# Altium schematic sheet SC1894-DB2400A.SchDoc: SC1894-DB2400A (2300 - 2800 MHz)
size B; Organization: Maxim Integrated; Address1: 160 Rio Robles; Address2: San Jose, CA. 95134; Address3: U.S.A.; Address4: 408-601-1000; Revision: 2.0; SheetNumber: 1; SheetTotal: 1; PageSetup: Record=PageOptions¦CenterHorizontal=True¦CenterVertical=True¦PrintScale=1.12¦XCorrection=1.00¦YCorrection=1.00¦PrintKind=1¦BorderSize=5000000¦LeftOffset=0¦BottomOffset=0¦Orientation=2¦PaperLength=1000¦PaperWidth=1000¦Scale=100¦PaperSource=15¦PrintQuality=600¦MediaType=1¦DitherType=10¦PaperKind=Tabloid¦PrintScaleMode=1
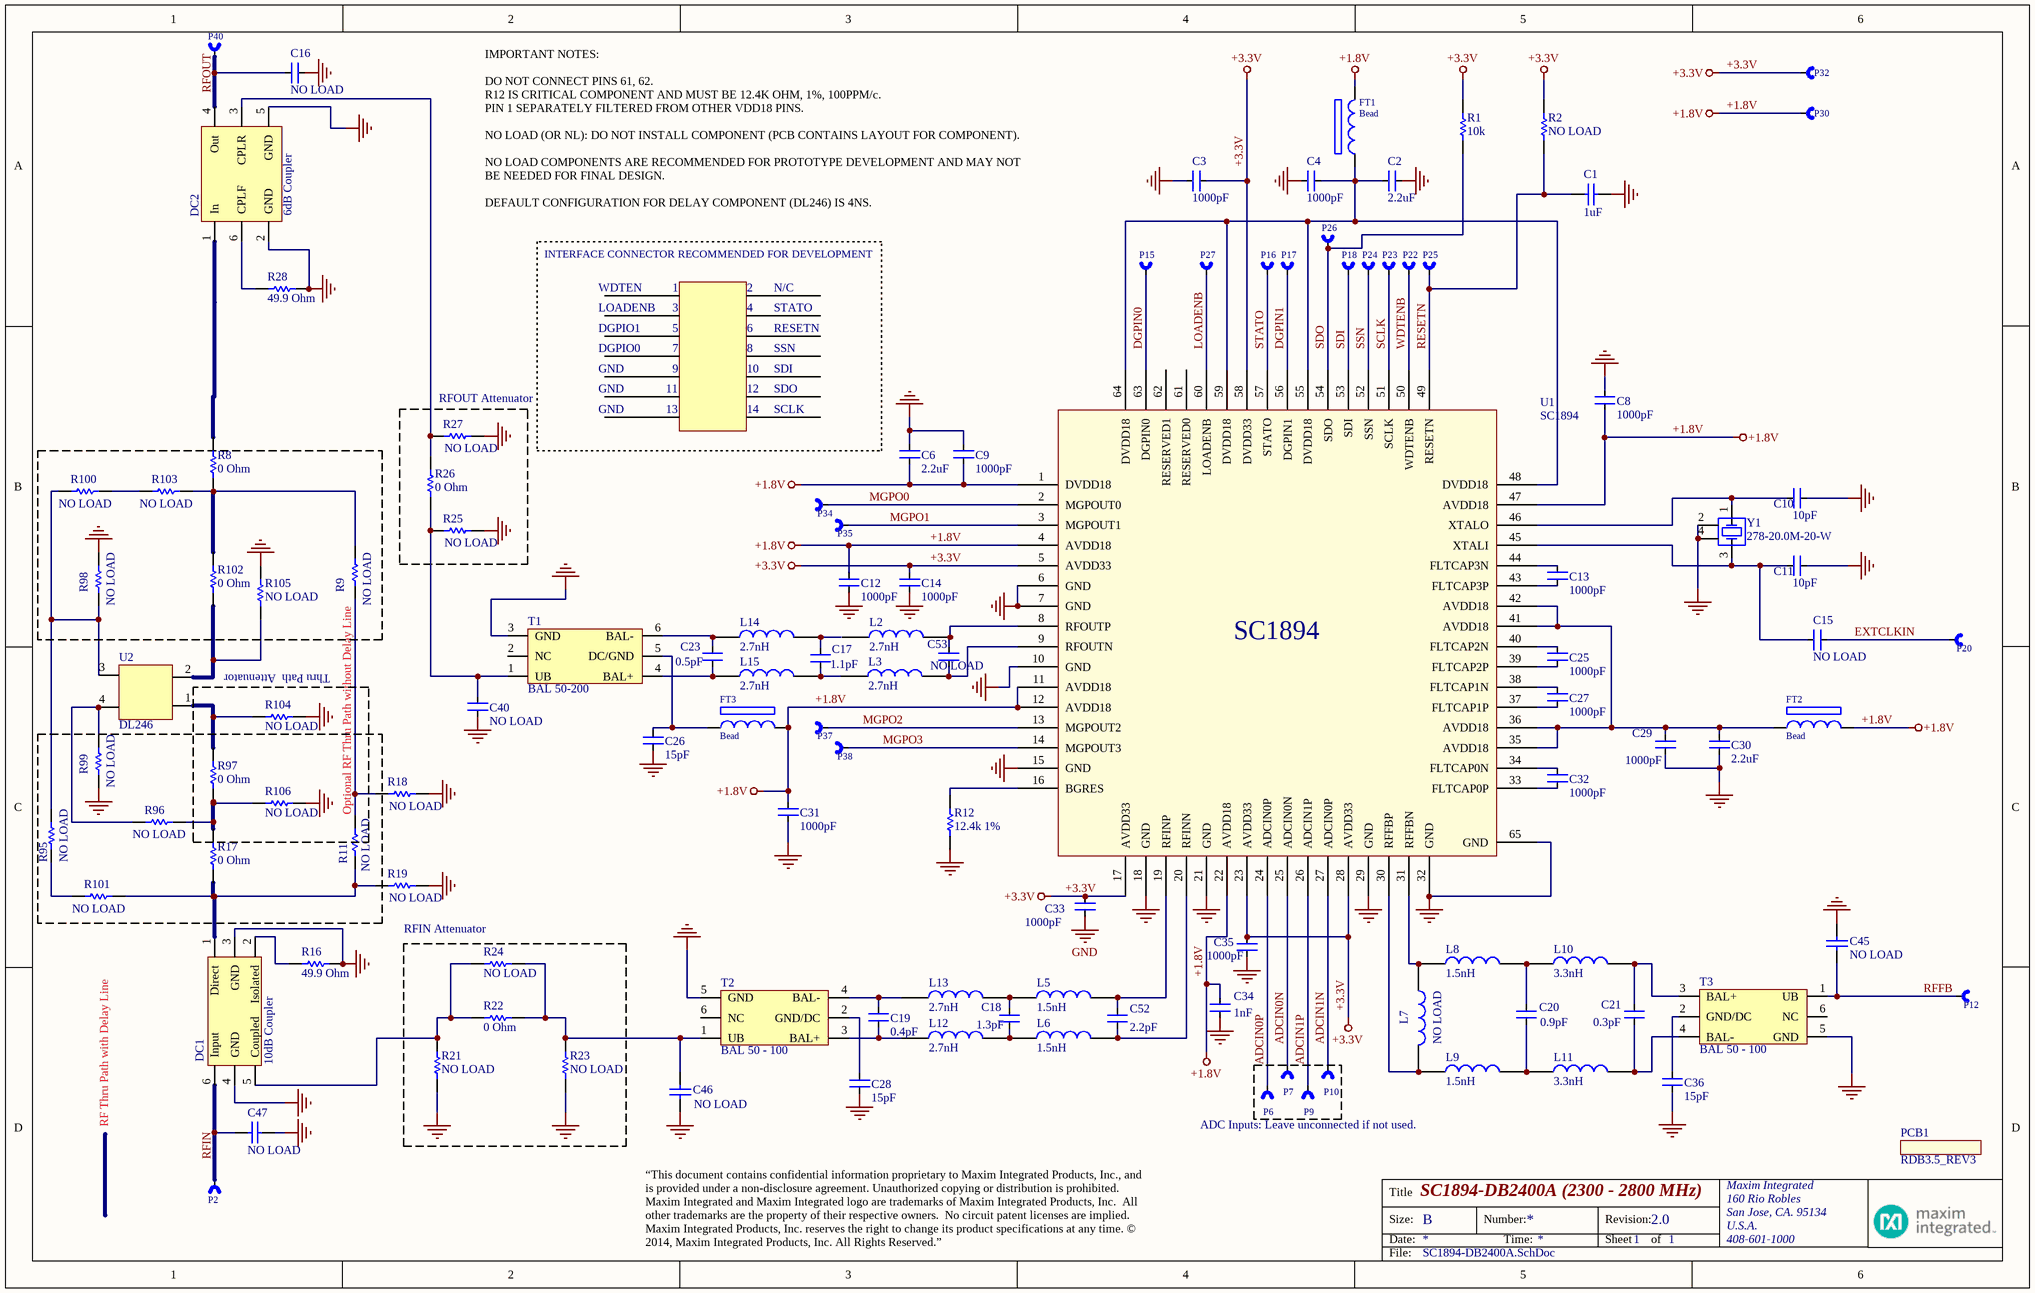
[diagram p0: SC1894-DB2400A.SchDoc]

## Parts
C1  1uF  [1608[0603]]
C2  2.2uF  [0603 SMD]
C3  1000pF  [0402 SMD]
C4  1000pF  [0402 SMD]
C6  2.2uF  [0603 SMD]
C8  1000pF  [0402 SMD]
C9  1000pF  [0402 SMD]
C10  10pF  [0402 SMD]
C11  10pF  [0402 SMD]
C12  1000pF  [0402 SMD]
C13  1000pF  [0402 SMD]
C14  1000pF  [0402 SMD]
C15  NO LOAD  [0402 SMD]
C16  NO LOAD  [0402 SMD]
C17  1.1pF  [0402 SMD]
C18  1.3pF  [0402 SMD]
C19  0.4pF  [0402 SMD]
C20  0.9pF  [0402 SMD]
C21  0.3pF  [0402 SMD]
C23  0.5pF  [0402 SMD]
C25  1000pF  [0402 SMD]
C26  15pF  [0402 SMD]
C27  1000pF  [0402 SMD]
C28  15pF  [0402 SMD]
C29  1000pF  [0402 SMD]
C30  2.2uF  [0603 SMD]
C31  1000pF  [0402 SMD]
C32  1000pF  [0402 SMD]
C33  1000pF  [0402 SMD]
C34  1nF  [0402 SMD]
C35  1000pF  [0402 SMD]
C36  15pF  [0402 SMD]
C40  NO LOAD  [0402 SMD]
C45  NO LOAD  [0402 SMD]
C46  NO LOAD  [0402 SMD]
C47  NO LOAD  [0402 SMD]
C52  2.2pF  [0402 SMD]
C53  NO LOAD  [0402 SMD]
DC1  10dB Coupler  [0805 COUPLER ANAREN]
DC2  6dB Coupler  [BDCN-7-25+]
FT1  Bead  [0603 SMD]
FT2  Bead  [0603 SMD]
FT3  Bead  [0402 SMD]
L2  2.7nH  [0402 SMD]
L3  2.7nH  [0402 SMD]
L5  1.5nH  [0402 SMD]
L6  1.5nH  [0402 SMD]
L7  NO LOAD  [0402 SMD]
L8  1.5nH  [0402 SMD]
L9  1.5nH  [0402 SMD]
L10  3.3nH  [0402 SMD]
L11  3.3nH  [0402 SMD]
L12  2.7nH  [0402 SMD]
L13  2.7nH  [0402 SMD]
L14  2.7nH  [0402 SMD]
L15  2.7nH  [0402 SMD]
P2  PORT 1-M  [PORT-1_M-PAD]  (value not drawn)
P6  PORT 1-M  [PORT-1_M-PAD]  (value not drawn)
P7  PORT 1-M  [PORT-1_M-PAD]  (value not drawn)
P9  PORT 1-M  [PORT-1_M-PAD]  (value not drawn)
P10  PORT 1-M  [PORT-1_M-PAD]  (value not drawn)
P12  PORT 1-M  [PORT-1_M-PAD]  (value not drawn)
P15  PORT 1-M  [PORT-1_M-PAD]  (value not drawn)
P16  PORT 1-M  [PORT-1_M-PAD]  (value not drawn)
P17  PORT 1-M  [PORT-1_M-PAD]  (value not drawn)
P18  PORT 1-M  [PORT-1_M-PAD]  (value not drawn)
P20  PORT 1-M  [PORT-1_M-PAD]  (value not drawn)
P22  PORT 1-M  [PORT-1_M-PAD]  (value not drawn)
P23  PORT 1-M  [PORT-1_M-PAD]  (value not drawn)
P24  PORT 1-M  [PORT-1_M-PAD]  (value not drawn)
P25  PORT 1-M  [PORT-1_M-PAD]  (value not drawn)
P26  PORT 1-M  [PORT-1_M-PAD]  (value not drawn)
P27  PORT 1-M  [PORT-1_M-PAD]  (value not drawn)
P30  PORT 1-M  [PORT-1_M-PAD]  (value not drawn)
P32  PORT 1-M  [PORT-1_M-PAD]  (value not drawn)
P34  PORT 1-M  [PORT-1_M-PAD]  (value not drawn)
P35  PORT 1-M  [PORT-1_M-PAD]  (value not drawn)
P37  PORT 1-M  [PORT-1_M-PAD]  (value not drawn)
P38  PORT 1-M  [PORT-1_M-PAD]  (value not drawn)
P40  PORT 1-M  [PORT-1_M-PAD]  (value not drawn)
PCB1  RDB3.5_REV3
R1  10k  [0402 SMD]
R2  NO LOAD  [0402 SMD]
R8  0 Ohm  [0402 SMD]
R9  NO LOAD  [0402 SMD]
R11  NO LOAD  [0402 SMD]
R12  12.4k 1%  [0402 SMD]
R16  49.9 Ohm  [0402 SMD]
R17  0 Ohm  [0402 SMD]
R18  NO LOAD  [0402 SMD]
R19  NO LOAD  [0402 SMD]
R21  NO LOAD  [0402 SMD]
R22  0 Ohm  [0201_SMT]
R23  NO LOAD  [0402 SMD]
R24  NO LOAD  [0201_SMT]
R25  NO LOAD  [0402 SMD]
R26  0 Ohm  [0402 SMD]
R27  NO LOAD  [0402 SMD]
R28  49.9 Ohm  [0402 SMD]
R95  NO LOAD  [0402 SMD]
R96  NO LOAD  [0402 SMD]
R97  0 Ohm  [0402 SMD]
R98  NO LOAD  [0402 SMD]
R99  NO LOAD  [0402 SMD]
R100  NO LOAD  [0402 SMD]
R101  NO LOAD  [0402 SMD]
R102  0 Ohm  [0402 SMD]
R103  NO LOAD  [0402 SMD]
R104  NO LOAD  [0402 SMD]
R105  NO LOAD  [0402 SMD]
R106  NO LOAD  [0402 SMD]
T1  BAL 50-200
T2  BAL 50 - 100  [0805 BALUN Anaren]
T3  BAL 50 - 100  [0805 BALUN Anaren]
U1  SC1894  [SC1894]
U2  DL246  [DL246-A]
Y1  278-20.0M-20-W  [278-20.0M]

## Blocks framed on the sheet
RFOUT Attenuator: R25-R27
Optional RF Thru Path without Delay Line: R11 R17 R95-R97 R99 R101 R106
RFIN Attenuator: R21-R24

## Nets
+1.8V: C6.2 C8.2 C9.2 C12.1 C31.2 C34.2 FT1.2 FT2.2 FT3.2 P30.1(P*) U1.1(DVDD18) U1.4(AVDD18) U1.11(AVDD18) U1.12(AVDD18) U1.22(AVDD18) U1.47(AVDD18)
+3.3V: C3.2 C14.1 C33.1 C35.2 P32.1(P*) R1.2 R2.2 U1.5(AVDD33) U1.17(AVDD33) U1.23(AVDD33) U1.28(AVDD33) U1.58(DVDD33)
GND: C1.1 C2.2 C3.1 C4.1 C6.1 C8.1 C9.1 C10.2 C11.2 C12.2 C14.2 C16.2 C26.2 C28.2 C29.2 C30.2 C31.1 C33.2 C34.1 C35.1 C36.2 C40.2 C45.1 C46.1 C47.1 DC1.3(GND) DC1.4(GND) DC2.2(GND) DC2.5(GND) R12.1 R16.2 R18.2 R19.2 R21.1 R23.1 R25.2 R27.2 R28.2 R98.1 R99.2 R104.2 R105.1 R106.2 T1.3(GND) T2.5(GND) T3.5(GND) U1.6(GND) U1.7(GND) U1.10(GND) U1.15(GND) U1.18(GND) U1.21(GND) U1.29(GND) U1.32(GND) U1.65(GND) Y1.2(SHIELD1) Y1.4(SHIELD2)
ADCIN0N: P7.1(P*) U1.25(ADCIN0N)
ADCIN0P: P6.1(P*) U1.24(ADCIN0P)
ADCIN1N: P10.1(P*) U1.27(ADCIN0P)
ADCIN1P: P9.1(P*) U1.26(ADCIN1P)
DGPIN0: P15.1(P*) U1.63(DGPIN0)
DGPIN1: P17.1(P*) U1.56(DGPIN1)
EXTCLKIN: C15.2 P20.1(P*)
LOADENB: P27.1(P*) U1.60(LOADENB)
MGPO0: P34.1(P*) U1.2(MGPOUT0)
MGPO1: P35.1(P*) U1.3(MGPOUT1)
MGPO2: P37.1(P*) U1.13(MGPOUT2)
MGPO3: P38.1(P*) U1.14(MGPOUT3)
RESETN: C1.2 P25.1(P*) R2.1 U1.49(RESETN)
RFFB: C45.2 P12.1(P*) T3.1(UB)
RFIN: C47.2 DC1.6(Input) P2.1(P*)
RFOUT: C16.1 DC2.4(Out) P40.1(P*)
SCLK: P23.1(P*) U1.51(SCLK)
SDI: P18.1(P*) U1.53(SDI)
SDO: P26.1(P*) R1.1 U1.54(SDO)
SSN: P24.1(P*) U1.52(SSN)
STATO: P16.1(P*) U1.57(STATO)
WDTENB: P22.1(P*) U1.50(WDTENB)
NetC2_1: C2.1 C4.2 FT1.1 U1.48(DVDD18) U1.55(DVDD18) U1.59(DVDD18) U1.64(DVDD18)
NetC10_1: C10.1 U1.46(XTALO) Y1.1(OSC1)
NetC11_1: C11.1 C15.1 U1.45(XTALI) Y1.3(OSC2)
NetC13_1: C13.1 U1.44(FLTCAP3N)
NetC13_2: C13.2 U1.43(FLTCAP3P)
NetC17_1: C17.1 L14.2
NetC17_2: C17.2 L3.1 L15.2
NetC18_1: C18.1 L5.1 L13.2
NetC18_2: C18.2 L6.1 L12.2
NetC19_1: C19.1 L13.1 T2.4(BAL-)
NetC19_2: C19.2 L12.1 T2.3(BAL+)
NetC20_1: C20.1 L8.2 L10.1
NetC20_2: C20.2 L9.2 L11.1
NetC21_1: C21.1 L10.2 T3.3(BAL+)
NetC21_2: C21.2 L11.2 T3.4(BAL-)
NetC23_1: C23.1 L14.1 T1.6(BAL-)
NetC23_2: C23.2 L15.1 T1.4(BAL+)
NetC25_1: C25.1 U1.40(FLTCAP2N)
NetC25_2: C25.2 U1.39(FLTCAP2P)
NetC26_1: C26.1 FT3.1 T1.5(DC/GND)
NetC27_1: C27.1 U1.38(FLTCAP1N)
NetC27_2: C27.2 U1.37(FLTCAP1P)
NetC28_1: C28.1 T2.2(GND/DC)
NetC29_1: C29.1 C30.1 FT2.1 U1.35(AVDD18) U1.36(AVDD18) U1.41(AVDD18) U1.42(AVDD18)
NetC32_1: C32.1 U1.34(FLTCAP0N)
NetC32_2: C32.2 U1.33(FLTCAP0P)
NetC36_1: C36.1 T3.2(GND/DC)
NetC40_1: C40.1 R25.1 R26.1 T1.1(UB)
NetC46_2: C46.2 R22.2 R23.2 R24.2 T2.1(UB)
NetC52_1: C52.1 L5.2 U1.19(RFINP)
NetC52_2: C52.2 L6.2 U1.20(RFINN)
NetC53_1: C53.1 L2.2 U1.8(RFOUTP)
NetC53_2: C53.2 L3.2 U1.9(RFOUTN)
NetDC1_1: DC1.1(Direct) R11.1 R17.1 R19.1 R101.1
NetDC1_2: DC1.2(Isolated) R16.1
NetDC1_5: DC1.5(Coupled) R21.2 R22.1 R24.1
NetDC2_1: DC2.1(In) R8.2
NetDC2_3: DC2.3(CPLR) R26.2 R27.1
NetDC2_6: DC2.6(CPLF) R28.1
NetL7_1: L7.1 L8.1 U1.31(RFFBN)
NetL7_2: L7.2 L9.1 U1.30(RFFBP)
NetR8_1: R8.1 R9.2 R102.2 R103.2
NetR9_1: R9.1 R11.2 R18.1
NetR12_2: R12.2 U1.16(BGRES)
NetR17_2: R17.2 R96.1 R97.1 R106.1
NetR95_1: R95.1 R98.2 R100.1 U2.3(2ns_B)
NetR95_2: R95.2 R101.2
NetR96_2: R96.2 R99.1 U2.4(2ns_A)
NetR97_2: R97.2 R104.1 U2.1(4ns_A)
NetR100_2: R100.2 R103.1
NetR102_1: R102.1 R105.2 U2.2(4ns_B)

Not connected (* = marked no-connect by the designer): L2 1; T1 2(NC); T2 6(NC); T3 6(NC); U1 61(RESERVED0) 62(RESERVED1)

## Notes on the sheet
- IMPORTANT NOTES:
  DO NOT CONNECT PINS 61, 62.
  R12 IS CRITICAL COMPONENT AND MUST BE 12.4K OHM, 1%, 100PPM/c.
  PIN 1 SEPARATELY FILTERED FROM OTHER VDD18 PINS.
  NO LOAD (OR NL): DO NOT INSTALL COMPONENT (PCB CONTAINS LAYOUT FOR COMPONENT).
  NO LOAD COMPONENTS ARE RECOMMENDED FOR PROTOTYPE DEVELOPMENT AND MAY NOT BE NEEDED FOR FINAL DESIGN.
  DEFAULT CONFIGURATION FOR DELAY COMPONENT (DL246) IS 4NS.
- INTERFACE CONNECTOR RECOMMENDED FOR DEVELOPMENT
- WDTEN
- 1
- 2
- N/C
- LOADENB
- DGPIO1
- DGPIO0
- GND
- 3
- 5
- 7
- 9
- 4
- 6
- 8
- 10
- STATO
- RESETN
- SSN
- SDI
- 11
- 13
- 12
- 14
- SDO
- SCLK
- Thru Path  Attenuator
- RF Thru Path with Delay Line
- ADC Inputs: Leave unconnected if not used.
- “This document contains confidential information proprietary to Maxim Integrated Products, Inc., and is provided under a non-disclosure agreement. Unauthorized copying or distribution is prohibited.  Maxim Integrated and Maxim Integrated logo are trademarks of Maxim Integrated Products, Inc.  All other trademarks are the property of their respective owners.  No circuit patent licenses are implied.  Maxim Integrated Products, Inc. reserves the right to change its product specifications at any time. © 2014, Maxim Integrated Products, Inc. All Rights Reserved.”

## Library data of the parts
C1 = 1u: 1uF 0603 ceramic capacitor
C2 C6 C30 = Cap 2.2uF 0603: 2.2uF 0603
C3 C4 C8 C9 C12-C14 C25 C27 C29 C31-C35 = Cap 1000pF: 1000pF 0402
C10 C11 C15 = Cap 10pF: 10pF 0402
C16 = Cap 0.9pF: 0.9pF 0402
C17 = Cap 1.1pF: 1.1pF 0402; Part Substitution Allowed?: No
C18 = Cap 1.3pF: 1.3pF 0402; Part Substitution Allowed?: No
C19 = Cap 0.4pF: 0.4pF 0402; Part Substitution Allowed?: No
C20 = Cap 0.9pF: 0.9pF 0402; Part Substitution Allowed?: No
C21 = Cap 0.3pF: 0.3pF 0402; Part Substitution Allowed?: No
C23 = Cap 0.5pF: 0.5pF 0402; Part Substitution Allowed?: No
C26 C28 C36 = Cap 15pF: 15pF 0402; Part Substitution Allowed?: Yes
C40 C53 = Cap No Load 0402: 0402 Cap No Load
C45-C47 = Capacitor: Generic Capacitor
C52 = Cap 2.2pF: 2.2pF 0402; Part Substitution Allowed?: No
DC1 = DC2337J5010AHF: Anaren 2300 - 3700 MHz 0805 10dB Coupler; Part Substitution Allowed?: No
DC2 = BDCN-7-25+: Mini Circuits Balun; Manufacturer 1: Mini-Circuits; Part Substitution Allowed?: No
FT1 FT2 = Bead 0603: Part Substitution Allowed?: No; Value: 120mH
FT3 = Bead 0402: Bead 0402 470 ohm; Part Substitution Allowed?: No; Value: 470mH
L2 L3 L12-L15 = 2.7nH: Part Substitution Allowed?: No
L5 L6 L8 L9 = 1.5nH: Part Substitution Allowed?: No
L7 = Inductor: SMT Inductor
L10 L11 = 3.3nH: Part Substitution Allowed?: No
P2 P6 P7 P9 P10 P12 P15-P18 P20 P22-P27 P30 P32 P34 P35 P37 P38 P40 = PORT 1-M: Ports of RDB Daughterboards
PCB1 = RDB3.5_REV2: Printed Circuit Board (RDB3.5 REV2)
R1 = 10k Ohm 0402
R2 R11 R21 R23 = RES NL 0402: NO LOAD RESISTOR 0402
R8 R17 R26 R97 R102 = 0 Ohm 0402
R9 R18 R19 R25 R27 R95 R96 R98-R101 R103-R106 = Resistor: Resistor Generic
R12 = 12.4k Ohm 0402
R16 R28 = 49.9 Ohm 0402
R22 = 0 Ohm 0201
R24 = RES NL 0201: NO LOAD RESISTOR 0201
T1 = DXP18BN5014T
T2 T3 = BD2040J50100A00: Anaren 2000 - 4000 MHz 50Ohm UnBal - 100 Dif Balun; Part Substitution Allowed?: No
U1 = SC1894: SC1894: Adaptive RF Power Amplifier Linearizer; Manufacturer 1: Scintera; Manufacturer Part Number 1: SC1894A-00A00
U2 = DL246: Kyocera Delay Line DL246; Part Substitution Allowed?: No
Y1 = 278-20.0M-20-W: Crystal 20MHz 278-20.0M-20-W; Manufacturer 1: Oscilent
